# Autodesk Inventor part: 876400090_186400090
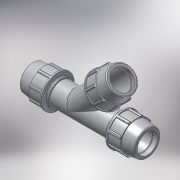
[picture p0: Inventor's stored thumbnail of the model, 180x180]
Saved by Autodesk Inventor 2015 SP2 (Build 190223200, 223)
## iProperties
Created: 2017-02
Part Number: 876400090_186400090
Material: PVC-Piping
Description: PLASSON 45° TEE 90-90-90
Document SubType Name: Modeling
Designer: KIM
Mass: 92.6774 g
Surface Area: 199.44 cm^2
Volume: 66.1981 cm^3
Density: 1.4 g/cm^3
Appearance: Smooth - White
Author: KIM
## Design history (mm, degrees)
derived "87640.ipt"
feature "Solid1::87640.ipt"
feature "Solid3::87640.ipt"
tag "TaggingFeature1"
body "Solid1"
other parameters: "d4" = 21.625, "d5" = 51.9, "d7" = 152, "d11" = 8.65, "d13" = 120 deg, "d14" = 117, "d15" = 8 deg, "d16" = 121.6, "d18" = 4.5, "d19" = 35 deg, "d20" = 17.5 deg, "d21" = 141.36, "d23" = 0, "d25" = 360 deg, "d27" = 3.04, "d33" = 1.8, "d42" = 62.28, "d43" = 4.56, "d46" = 2.7, "d68" = 7.785, "d91" = 106.4, "d93" = 164, "d95" = 81, "d134" = 259.5, "d138" = 45 deg, "d141" = 233, "d144" = 0, "d146" = 0, "d150" = 4.5, "d158" = 1.8, "d159" = 6.08, "d160" = 0, "d165" = 311.6, "d166" = 141.36, "d167" = 35 deg, "d168" = 17.5 deg, "d170" = 0, "d172" = 360 deg, "d174" = 4.56, "d177" = 3.04, "d180" = 6.08, "d181" = 0, "E_" = 152, "A_" = 233, "l_" = 164, "H_" = 519
